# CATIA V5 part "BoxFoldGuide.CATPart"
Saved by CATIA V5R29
Part number: BoxFoldGuide
Source: Unknown
Bounding box of the stored display mesh (mm): x -50 to 50, y -1500 to 0, z 611 to 1381
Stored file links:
  C:\가치같이\SmartFactory_BoxErectorConveyor\Boxing(under)\BoxFoldGuide.CATPart
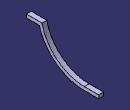
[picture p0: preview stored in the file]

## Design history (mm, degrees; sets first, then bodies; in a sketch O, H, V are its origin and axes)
Body1 (main body)
  Solid1 "PartBody": solid without history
